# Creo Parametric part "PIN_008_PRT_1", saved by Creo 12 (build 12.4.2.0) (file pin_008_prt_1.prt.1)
Units: Custom; MM, KILOGRAM, SECS

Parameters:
  PTC_WM_ITERATION = "0"
  PTC_WM_VERSION = "-.0"
  PTC_WM_LIFECYCLE_STATE = "In Work"
  PTC_WM_LIFECYCLE = "MO_CADDocument"
  PTC_WM_CREATED_BY = "Maximilian Roepper (Z0017RMS: MO)"
  PTC_WM_CREATED_ON = "18-Sep-26 11:36:42 AM"
  PTC_WM_MODIFIED_BY = "Maximilian Roepper (Z0017RMS: MO)"
  PTC_WM_MODIFIED_ON = "18-Sep-26 11:36:46 AM"
  PDMLINKNUMBER = "PDM000071454925"
  PTC_WM_NAME = "pin_008_prt_1.prt"
  PTC_WM_NUMBER = "PDM000071454925"

Other parameters: WEIGHT, WEIGHT_FACTOR, WEIGHT_ADD, _MASS_TEMP, _DIFF_TEMP, MC_ERRORS, SUPPLIER

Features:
  1. coordinate system
  2. datum plane "PRT_YZ"
  3. datum plane "PRT_XY"
  4. datum plane "PRT_XZ"
  5. coordinate system
  6. datum axis
  7. datum axis
  8. datum axis
  9. coordinate system
  10. imported feature
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
Other named items: PRT, SIEMENS_MO, DRW_VIEW_ORG, PRT_X, PRT_Y, PRT_Z, CS0, ROUGH_GROB

Layers: 00_STD_CSYS-KSYS, 01_STD_PLANES-EBENEN, 02_STD_AXES-ACHSEN, 03_STD_CSYS-KSYS, 24_IMPORT_FEAT-IMPORT_KE

Surfaces: 9 plane, 1 cylinder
